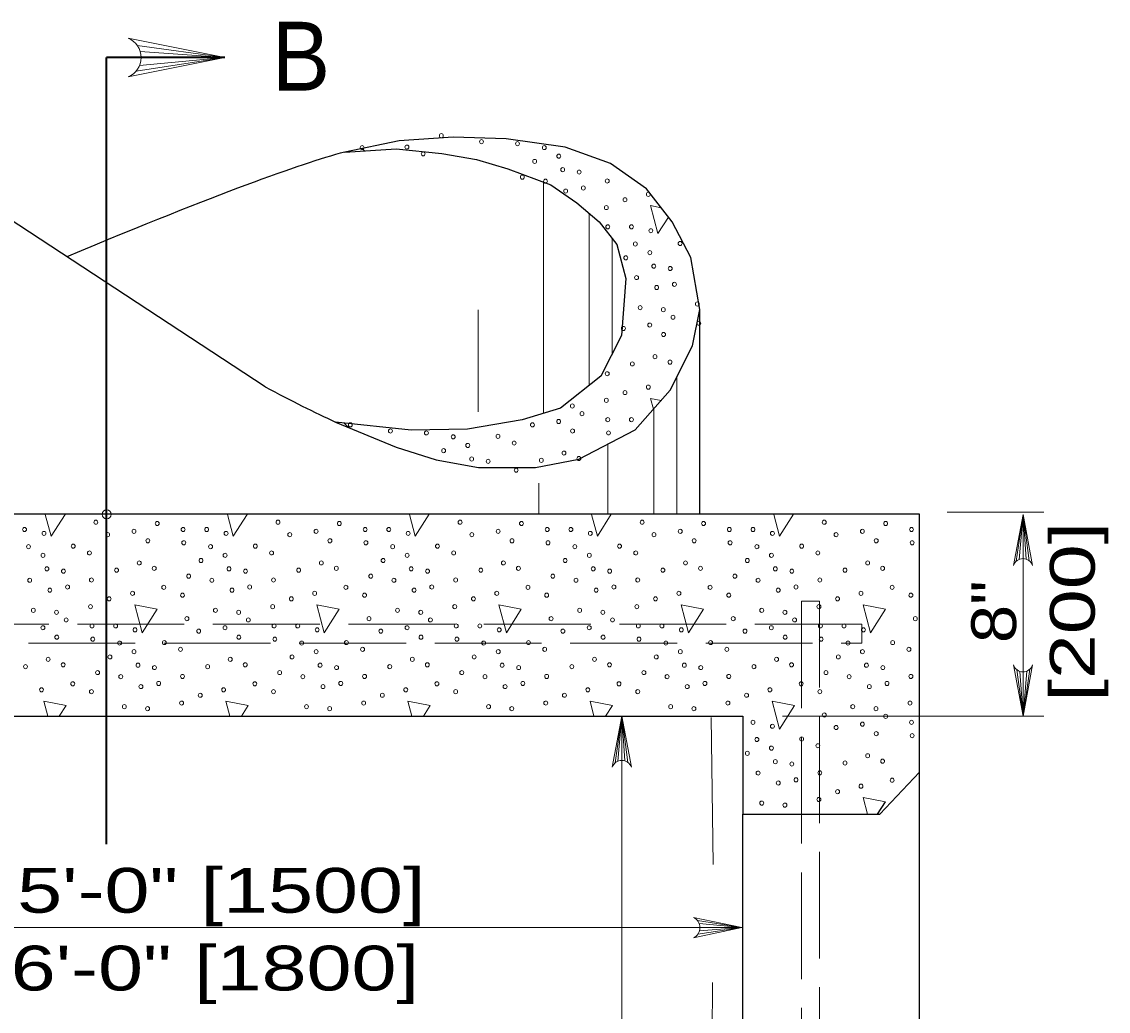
# Model space of a CAD drawing. Extents: x 1329.9 to 1363.9, y 715.5 to 737.5.
# Drawn here: x 1350.356 to 1354.141, y 722.725 to 726.171 of the extents above; entities that cross this region are included whole.
import ezdxf
from ezdxf.enums import TextEntityAlignment as Align

# ---------------------------------------------------------------- set-up
doc = ezdxf.new("R2010")
doc.units = 0
doc.header["$LTSCALE"] = 0.062
doc.header["$PDMODE"] = 32
doc.header["$PDSIZE"] = 0.031
doc.linetypes.add('LONG_DASHED', pattern=[7.5, 6, -1.5])
doc.layers.add('1', color=7, linetype='Continuous', lineweight=13)

msp = doc.modelspace()

# ---------------------------------------------------------------- linework, layer by layer
at = {"layer": '1'}
for p, q in [((1350.75792, 726.089), (1351.06258, 726.04642)), ((1350.75433, 725.99925), (1351.06258, 726.04642)), ((1350.766, 726.019), (1351.06258, 726.04642)), ((1350.76825, 726.06792), (1351.06258, 726.04642)), ((1350.77142, 726.04642), (1351.06258, 726.04642)), ((1351.54967, 725.72158), (1351.54183, 725.72975)), ((1352.17275, 724.80717), (1352.17275, 725.61258)), ((1352.58308, 725.5235), (1352.54617, 725.53067)), ((1352.33283, 724.90492), (1352.33283, 725.503)), ((1352.41283, 725.01583), (1352.41283, 725.41542)), ((1351.946, 724.8125), (1351.946, 725.1675)), ((1352.6375, 724.4555), (1352.6375, 724.93308)), ((1352.54617, 724.85908), (1352.55608, 724.82142)), ((1352.583, 724.85192), (1352.54617, 724.85908)), ((1352.5575, 724.4555), (1352.5575, 724.82267)), ((1351.45992, 724.77208), (1351.4565, 724.77592)), ((1351.494, 724.75825), (1351.47933, 724.7735)), ((1352.39742, 724.4555), (1352.39742, 724.69983)), ((1352.15733, 724.4555), (1352.15733, 724.56417)), ((1353.57942, 724.46342), (1353.916, 724.46342)), ((1353.82008, 724.29208), (1353.84367, 724.45525)), ((1353.83, 724.29825), (1353.84367, 724.45525)), ((1353.84367, 723.75258), (1353.84367, 724.45525)), ((1353.84367, 724.30108), (1353.84367, 724.45525)), ((1353.85442, 724.29942), (1353.84367, 724.45525)), ((1353.865, 724.294), (1353.84367, 724.45525)), ((1353.82233, 723.91383), (1353.84367, 723.75258)), ((1353.83292, 723.90833), (1353.84367, 723.75258)), ((1353.86717, 723.91575), (1353.84367, 723.75258)), ((1353.85733, 723.9095), (1353.84367, 723.75258)), ((1353.84367, 723.90667), (1353.84367, 723.75258)), ((1350.43217, 723.80475), (1350.44592, 723.75258)), ((1351.0665, 723.80475), (1351.08008, 723.75258)), ((1351.70092, 723.80475), (1351.71458, 723.75258)), ((1352.33533, 723.80475), (1352.34892, 723.75258)), ((1352.4225, 723.58942), (1352.44608, 723.75258)), ((1352.43242, 723.59558), (1352.44608, 723.75258)), ((1352.44608, 719.17433), (1352.44608, 723.75258)), ((1352.44608, 723.5985), (1352.44608, 723.75258)), ((1352.45683, 723.59683), (1352.44608, 723.75258)), ((1352.46733, 723.59133), (1352.44608, 723.75258)), ((1352.76375, 723.23608), (1352.75717, 723.74783)), ((1353.0055, 723.75258), (1353.916, 723.75258)), ((1353.28683, 723.469), (1353.30225, 723.41067)), ((1353.36475, 723.45375), (1353.28683, 723.469)), ((1348.49092, 723.01592), (1352.86367, 723.01592)), ((1352.70958, 723.04092), (1352.86367, 723.01592)), ((1352.71133, 722.99342), (1352.86367, 723.01592)), ((1352.71542, 723.03042), (1352.86367, 723.01592)), ((1352.7165, 723.00458), (1352.86367, 723.01592)), ((1352.71808, 723.01592), (1352.86367, 723.01592)), ((1352.75967, 722.31133), (1352.76208, 722.82492))]:
    msp.add_line(p, q, dxfattribs=at)
at = {"layer": '1', "lineweight": 35}
for p, q in [((1350.65133, 724.20842), (1350.65133, 726.04642)), ((1351.06258, 726.04642), (1350.65133, 726.04642)), ((1350.65133, 723.30692), (1350.65133, 724.20842))]:
    msp.add_line(p, q, dxfattribs=at)
at = {"layer": '1', "lineweight": 25}
for p, q in [((1351.20408, 724.89942), (1349.977, 725.70392)), ((1352.7175, 724.4555), (1352.7175, 725.16917)), ((1353.483, 719.36825), (1353.483, 723.55683)), ((1353.33733, 723.41067), (1353.36475, 723.45375)), ((1352.86742, 719.51625), (1352.86742, 723.41067))]:
    msp.add_line(p, q, dxfattribs=at)
at = {"layer": '1'}
for points in [[(1350.72608, 725.97908), (1351.06258, 726.04642), (1350.72608, 726.11367)], [(1351.48092, 725.71742), (1351.67067, 725.75608), (1351.859, 725.76933), (1352.04317, 725.76342), (1352.24817, 725.73458), (1352.40642, 725.677), (1352.53183, 725.58975), (1352.62117, 725.47442), (1352.6865, 725.35), (1352.7175, 725.16917), (1352.69208, 725.04292), (1352.615, 724.88808), (1352.49258, 724.74925), (1352.29633, 724.64725), (1352.14525, 724.619), (1351.94675, 724.61817), (1351.79875, 724.64583), (1351.6605, 724.68925), (1351.44875, 724.777)], [(1351.44875, 724.777), (1351.71258, 724.749), (1351.90892, 724.75233), (1352.09883, 724.78517), (1352.23275, 724.82492), (1352.37283, 724.93675), (1352.44458, 725.07883), (1352.46008, 725.27642), (1352.42883, 725.39508), (1352.36667, 725.47442), (1352.28883, 725.54033), (1352.19833, 725.60308), (1352.049, 725.65883), (1351.93983, 725.69192), (1351.8185, 725.71175), (1351.65967, 725.72833), (1351.48092, 725.71742)], [(1352.54617, 725.53067), (1352.57183, 725.43333), (1352.60833, 725.491)], [(1350.43758, 724.45542), (1350.45775, 724.37908), (1350.50633, 724.45542)], [(1351.072, 724.45542), (1351.09217, 724.37908), (1351.14067, 724.45542)], [(1351.70633, 724.45542), (1351.7265, 724.37908), (1351.77508, 724.4555)], [(1352.34075, 724.45542), (1352.36092, 724.37908), (1352.40942, 724.4555)], [(1352.97517, 724.45542), (1352.99533, 724.37908), (1353.04383, 724.4555)], [(1353.81, 724.27717), (1353.84367, 724.45525), (1353.87733, 724.27717)], [(1353.87733, 723.93067), (1353.84367, 723.75258), (1353.81, 723.93067)], [(1350.4865, 723.75267), (1350.50992, 723.78958), (1350.43217, 723.80475)], [(1351.12083, 723.75258), (1351.14442, 723.78958), (1351.0665, 723.80475)], [(1351.75525, 723.75258), (1351.77875, 723.78958), (1351.70092, 723.80475)], [(1352.38958, 723.75258), (1352.41317, 723.78958), (1352.33533, 723.80475)], [(1352.41242, 723.5745), (1352.44608, 723.75258), (1352.47975, 723.5745)], [(1352.69542, 723.05158), (1352.86367, 723.01592), (1352.69542, 722.98033)]]:
    msp.add_lwpolyline(points, dxfattribs=at)
at = {"layer": '1', "lineweight": 25}
for points in [[(1351.44875, 724.777), (1351.6605, 724.68925), (1351.79875, 724.64583), (1351.94675, 724.61817), (1352.14525, 724.619), (1352.29633, 724.64725), (1352.49258, 724.74925), (1352.615, 724.88808), (1352.69208, 725.04292), (1352.7175, 725.16917), (1352.6865, 725.35), (1352.62117, 725.47442), (1352.53183, 725.58975), (1352.40642, 725.677), (1352.24817, 725.73458), (1352.04317, 725.76342), (1351.859, 725.76933), (1351.67067, 725.75608), (1351.48092, 725.71742)], [(1351.44875, 724.777), (1351.6605, 724.68925), (1351.79875, 724.64583), (1351.94675, 724.61817), (1352.14525, 724.619), (1352.29633, 724.64725), (1352.49258, 724.74925), (1352.615, 724.88808), (1352.69208, 725.04292), (1352.7175, 725.16917), (1352.6865, 725.35), (1352.62117, 725.47442), (1352.53183, 725.58975), (1352.40642, 725.677), (1352.24817, 725.73458), (1352.04317, 725.76342), (1351.859, 725.76933), (1351.67067, 725.75608), (1351.48092, 725.71742)], [(1351.48092, 725.71742), (1351.65967, 725.72833), (1351.8185, 725.71175), (1351.93983, 725.69192), (1352.049, 725.65883), (1352.19833, 725.60308), (1352.28883, 725.54033), (1352.36667, 725.47442), (1352.42883, 725.39508), (1352.46008, 725.27642), (1352.44458, 725.07883), (1352.37283, 724.93675), (1352.23275, 724.82492), (1352.09883, 724.78517), (1351.90892, 724.75233), (1351.71258, 724.749), (1351.44875, 724.777)], [(1351.48092, 725.71742), (1351.65967, 725.72833), (1351.8185, 725.71175), (1351.93983, 725.69192), (1352.049, 725.65883), (1352.19833, 725.60308), (1352.28883, 725.54033), (1352.36667, 725.47442), (1352.42883, 725.39508), (1352.46008, 725.27642), (1352.44458, 725.07883), (1352.37283, 724.93675), (1352.23275, 724.82492), (1352.09883, 724.78517), (1351.90892, 724.75233), (1351.71258, 724.749), (1351.44875, 724.777)], [(1353.483, 723.55867), (1353.483, 724.4555), (1347.83075, 724.4555), (1347.83075, 723.58692)], [(1348.49467, 723.75258), (1352.86742, 723.75258), (1352.86742, 723.41067), (1353.34492, 723.41067), (1353.483, 723.55683)]]:
    msp.add_lwpolyline(points, dxfattribs=at)
at = {"layer": '1', "linetype": 'LONG_DASHED'}
for points in [[(1353.13433, 724.15242), (1353.07167, 724.15242), (1353.07167, 718.66), (1353.13433, 718.66)], [(1348.01858, 724.00633), (1353.28167, 724.00633), (1353.28167, 724.07267), (1348.01858, 724.07267)]]:
    msp.add_lwpolyline(points, close=True, dxfattribs=at)
at = {"layer": '1'}
for points in [[(1350.74925, 724.14058), (1350.77492, 724.04325), (1350.82717, 724.12542)], [(1351.38375, 724.14058), (1351.40942, 724.04325), (1351.46158, 724.12542)], [(1352.01808, 724.14058), (1352.04375, 724.04325), (1352.09592, 724.12542)], [(1352.6525, 724.14058), (1352.67817, 724.04325), (1352.73042, 724.12542)], [(1353.28683, 724.14058), (1353.3125, 724.04325), (1353.36475, 724.12542)], [(1352.96975, 723.80475), (1352.99533, 723.7075), (1353.04758, 723.78958)]]:
    msp.add_lwpolyline(points, close=True, dxfattribs=at)
msp.add_arc((1350.69893, 726.04646), 0.07261, 292.08605, 67.91218, dxfattribs=at)
for centre in [(1351.81734, 725.77454), (1351.69739, 725.73464), (1351.95723, 725.75339), (1352.08252, 725.74645), (1351.54154, 725.73285), (1351.7539, 725.71107), (1352.17594, 725.73285), (1352.22642, 725.7029), (1352.14247, 725.68477), (1352.09939, 725.63008), (1352.24017, 725.65577), (1352.29753, 725.64755), (1352.18017, 725.61587), (1352.31207, 725.5923), (1352.39517, 725.61671), (1352.25037, 725.58139), (1352.45708, 725.55117), (1352.5385, 725.5702), (1352.39206, 725.52396), (1352.39718, 725.45686), (1352.47944, 725.45686), (1352.54706, 725.44325), (1352.49314, 725.39702), (1352.64899, 725.39881), (1352.54362, 725.36708), (1352.45967, 725.34894), (1352.55737, 725.31995), (1352.49737, 725.28004), (1352.61473, 725.31172), (1352.56757, 725.24557), (1352.62927, 725.25648), (1352.50995, 725.17549), (1352.59078, 725.1685), (1352.70925, 725.18814), (1352.62446, 725.14191), (1352.45174, 725.1029), (1352.54336, 725.11471), (1352.71438, 725.12103), (1352.59163, 725.08174), (1352.48283, 724.97932), (1352.56165, 725.00467), (1352.61388, 724.98564), (1352.39517, 724.94506), (1352.45708, 724.87952), (1352.5385, 724.89855), (1352.27358, 724.83267), (1352.39206, 724.85232), (1352.30726, 724.80609), (1351.50014, 724.76708), (1352.13454, 724.76708), (1352.22616, 724.77888), (1352.39718, 724.78521), (1352.47944, 724.78521), (1351.64003, 724.74592), (1351.76532, 724.73898), (1351.85874, 724.72538), (1352.01459, 724.72717), (1352.27443, 724.74592), (1352.39972, 724.73898), (1351.82527, 724.6773), (1351.90923, 724.69543), (1352.0711, 724.7036), (1351.92297, 724.64831), (1351.98033, 724.64008), (1352.16563, 724.64349), (1352.24445, 724.66885), (1352.29668, 724.64982), (1352.07798, 724.60924), (1350.61375, 724.428), (1350.8276, 724.42346), (1351.24815, 724.428), (1351.462, 724.42346), (1351.88255, 724.428), (1352.0964, 724.42346), (1352.51695, 724.428), (1352.7308, 724.42346), (1353.15135, 724.428), (1353.36519, 724.42346), (1350.36539, 724.40259), (1350.433, 724.38898), (1350.65488, 724.38445), (1350.7465, 724.39626), (1350.91753, 724.40259), (1350.99979, 724.40259), (1351.0674, 724.38898), (1351.28928, 724.38445), (1351.3809, 724.39626), (1351.55192, 724.40259), (1351.63419, 724.40259), (1351.7018, 724.38898), (1351.92368, 724.38445), (1352.0153, 724.39626), (1352.18632, 724.40259), (1352.26858, 724.40259), (1352.3362, 724.38898), (1352.55808, 724.38445), (1352.6497, 724.39626), (1352.82072, 724.40259), (1352.90298, 724.40259), (1352.9706, 724.38898), (1353.19248, 724.38445), (1353.2841, 724.39626), (1353.45512, 724.40259), (1350.37908, 724.34275), (1350.53493, 724.34454), (1350.79477, 724.36329), (1350.92006, 724.35635), (1351.01348, 724.34275), (1351.16933, 724.34454), (1351.42917, 724.36329), (1351.55446, 724.35635), (1351.64788, 724.34275), (1351.80373, 724.34454), (1352.06357, 724.36329), (1352.18886, 724.35635), (1352.28228, 724.34275), (1352.43813, 724.34454), (1352.69797, 724.36329), (1352.82326, 724.35635), (1352.91667, 724.34275), (1353.07253, 724.34454), (1353.33236, 724.36329), (1353.45766, 724.35635), (1350.42957, 724.31281), (1350.59144, 724.32098), (1350.98001, 724.29467), (1351.06397, 724.31281), (1351.22584, 724.32098), (1351.61441, 724.29467), (1351.69837, 724.31281), (1351.86024, 724.32098), (1352.24881, 724.29467), (1352.33276, 724.31281), (1352.49464, 724.32098), (1352.88321, 724.29467), (1352.96716, 724.31281), (1353.12904, 724.32098), (1350.44331, 724.26568), (1350.50067, 724.25745), (1350.68597, 724.26087), (1350.76479, 724.28622), (1350.81703, 724.26719), (1351.07771, 724.26568), (1351.13507, 724.25745), (1351.32037, 724.26087), (1351.39919, 724.28622), (1351.45143, 724.26719), (1351.71211, 724.26568), (1351.76947, 724.25745), (1351.95477, 724.26087), (1352.03359, 724.28622), (1352.08582, 724.26719), (1352.34651, 724.26568), (1352.40387, 724.25745), (1352.58917, 724.26087), (1352.66799, 724.28622), (1352.72022, 724.26719), (1352.98091, 724.26568), (1353.03827, 724.25745), (1353.22357, 724.26087), (1353.30239, 724.28622), (1353.35462, 724.26719), (1350.38331, 724.22577), (1350.59832, 724.22661), (1350.93693, 724.23999), (1351.01771, 724.22577), (1351.23272, 724.22661), (1351.57133, 724.23999), (1351.65211, 724.22577), (1351.86712, 724.22661), (1352.20573, 724.23999), (1352.28651, 724.22577), (1352.50151, 724.22661), (1352.84012, 724.23999), (1352.9209, 724.22577), (1353.13591, 724.22661), (1350.45352, 724.1913), (1350.51521, 724.20221), (1350.85039, 724.20098), (1351.08791, 724.1913), (1351.14961, 724.20221), (1351.48478, 724.20098), (1351.72231, 724.1913), (1351.78401, 724.20221), (1352.11918, 724.20098), (1352.35671, 724.1913), (1352.41841, 724.20221), (1352.75358, 724.20098), (1352.99111, 724.1913), (1353.05281, 724.20221), (1353.38798, 724.20098), (1350.66022, 724.16107), (1350.74164, 724.1801), (1350.91552, 724.17378), (1351.29462, 724.16107), (1351.37604, 724.1801), (1351.54992, 724.17378), (1351.92902, 724.16107), (1352.01044, 724.1801), (1352.18431, 724.17378), (1352.56342, 724.16107), (1352.64484, 724.1801), (1352.81871, 724.17378), (1353.19782, 724.16107), (1353.27923, 724.1801), (1353.45311, 724.17378), (1350.39589, 724.12122), (1350.47672, 724.11423), (1350.5952, 724.13387), (1351.03029, 724.12122), (1351.11112, 724.11423), (1351.2296, 724.13387), (1351.66469, 724.12122), (1351.74552, 724.11423), (1351.864, 724.13387), (1352.29909, 724.12122), (1352.37992, 724.11423), (1352.49839, 724.13387), (1352.93349, 724.12122), (1353.01432, 724.11423), (1353.13279, 724.13387), (1350.5104, 724.08764), (1350.93095, 724.09217), (1351.1448, 724.08764), (1351.56535, 724.09217), (1351.7792, 724.08764), (1352.19975, 724.09217), (1352.4136, 724.08764), (1352.83415, 724.09217), (1353.048, 724.08764), (1353.46855, 724.09217), (1350.4293, 724.06044), (1350.60033, 724.06676), (1350.68259, 724.06676), (1350.7502, 724.05316), (1350.97208, 724.04863), (1351.0637, 724.06044), (1351.23473, 724.06676), (1351.31699, 724.06676), (1351.3846, 724.05316), (1351.60648, 724.04863), (1351.6981, 724.06044), (1351.86912, 724.06676), (1351.95138, 724.06676), (1352.019, 724.05316), (1352.24088, 724.04863), (1352.3325, 724.06044), (1352.50352, 724.06676), (1352.58578, 724.06676), (1352.6534, 724.05316), (1352.87528, 724.04863), (1352.9669, 724.06044), (1353.13792, 724.06676), (1353.22018, 724.06676), (1353.2878, 724.05316), (1350.47757, 724.02747), (1350.60286, 724.02053), (1350.69628, 724.00693), (1350.85213, 724.00872), (1351.11197, 724.02747), (1351.23726, 724.02053), (1351.33068, 724.00693), (1351.48653, 724.00872), (1351.74637, 724.02747), (1351.87166, 724.02053), (1351.96508, 724.00693), (1352.12093, 724.00872), (1352.38077, 724.02747), (1352.50606, 724.02053), (1352.59948, 724.00693), (1352.75533, 724.00872), (1353.01517, 724.02747), (1353.14046, 724.02053), (1353.23387, 724.00693), (1353.38972, 724.00872), (1350.66281, 723.95885), (1350.74677, 723.97699), (1350.90864, 723.98516), (1351.29721, 723.95885), (1351.38117, 723.97699), (1351.54304, 723.98516), (1351.93161, 723.95885), (1352.01556, 723.97699), (1352.17744, 723.98516), (1352.56601, 723.95885), (1352.64996, 723.97699), (1352.81184, 723.98516), (1353.20041, 723.95885), (1353.28436, 723.97699), (1353.44624, 723.98516), (1350.36877, 723.92505), (1350.4476, 723.9504), (1350.49983, 723.93137), (1350.76051, 723.92986), (1350.81787, 723.92163), (1351.00317, 723.92505), (1351.08199, 723.9504), (1351.13423, 723.93137), (1351.39491, 723.92986), (1351.45227, 723.92163), (1351.63757, 723.92505), (1351.71639, 723.9504), (1351.76862, 723.93137), (1352.02931, 723.92986), (1352.08667, 723.92163), (1352.27197, 723.92505), (1352.35079, 723.9504), (1352.40302, 723.93137), (1352.66371, 723.92986), (1352.72107, 723.92163), (1352.90637, 723.92505), (1352.98519, 723.9504), (1353.03742, 723.93137), (1353.29811, 723.92986), (1353.35547, 723.92163), (1350.61973, 723.90417), (1350.70051, 723.88995), (1350.91552, 723.89079), (1351.25413, 723.90417), (1351.33491, 723.88995), (1351.54992, 723.89079), (1351.88853, 723.90417), (1351.96931, 723.88995), (1352.18431, 723.89079), (1352.52292, 723.90417), (1352.6037, 723.88995), (1352.81871, 723.89079), (1353.15732, 723.90417), (1353.2381, 723.88995), (1353.45311, 723.89079), (1350.42444, 723.84428), (1350.53319, 723.86516), (1350.77072, 723.85547), (1350.83241, 723.86639), (1351.05884, 723.84428), (1351.16758, 723.86516), (1351.40511, 723.85547), (1351.46681, 723.86639), (1351.69324, 723.84428), (1351.80198, 723.86516), (1352.03951, 723.85547), (1352.10121, 723.86639), (1352.32764, 723.84428), (1352.43638, 723.86516), (1352.67391, 723.85547), (1352.73561, 723.86639), (1352.96203, 723.84428), (1353.07078, 723.86516), (1353.30831, 723.85547), (1353.37001, 723.86639), (1350.59832, 723.83796), (1350.97742, 723.82525), (1351.23272, 723.83796), (1351.61182, 723.82525), (1351.86712, 723.83796), (1352.24622, 723.82525), (1352.50151, 723.83796), (1352.88062, 723.82525), (1353.13591, 723.83796), (1350.71309, 723.7854), (1350.79392, 723.7784), (1350.9124, 723.79805), (1351.34749, 723.7854), (1351.42832, 723.7784), (1351.5468, 723.79805), (1351.98189, 723.7854), (1352.06272, 723.7784), (1352.1812, 723.79805), (1352.61629, 723.7854), (1352.69712, 723.7784), (1352.81559, 723.79805), (1353.25069, 723.7854), (1353.33152, 723.7784), (1353.44999, 723.79805), (1352.90298, 723.73094), (1353.15135, 723.75635), (1353.36519, 723.75182), (1353.45512, 723.73094), (1352.9706, 723.71734), (1353.19248, 723.71281), (1353.2841, 723.72462), (1353.33236, 723.69165), (1352.91667, 723.67111), (1353.07253, 723.6729), (1353.45766, 723.68471), (1352.88321, 723.62303), (1352.96716, 723.64116), (1353.12904, 723.64933), (1353.30239, 723.61458), (1352.98091, 723.59404), (1353.03827, 723.58581), (1353.22357, 723.58922), (1353.35462, 723.59555), (1352.9209, 723.55413), (1353.13591, 723.55497), (1352.99111, 723.51965), (1353.05281, 723.53057), (1353.27923, 723.50846), (1353.38798, 723.52933), (1353.13279, 723.46223), (1353.19782, 723.48943), (1352.93349, 723.44958), (1353.01432, 723.44258)]:
    msp.add_ellipse(centre, major_axis=(0, 0.00718), ratio=0.944544, dxfattribs=at)
for centre, major_axis, start_param, end_param in [((1353.84366, 724.26268), (0, 0.03844), 5.0978942, 7.4685073), ((1353.84365, 723.94513), (0, -0.03844), 5.0978942, 7.4685073), ((1352.44606, 723.56003), (0, 0.03844), 5.0978942, 7.4685073), ((1352.6818, 723.01594), (0, -0.03844), 0.3855052, 2.7561184)]:
    msp.add_ellipse(centre, major_axis=major_axis, ratio=0.944544, start_param=start_param, end_param=end_param, dxfattribs=at)
at = {"layer": '1', "lineweight": 25}
for points in [[(1351.48092, 725.71742), (1351.31592, 725.67217), (1351.05092, 725.57733), (1350.51292, 725.35258)], [(1351.20408, 724.89942), (1351.29425, 724.85117), (1351.37567, 724.81075), (1351.44875, 724.777)]]:
    msp.add_open_spline(points, degree=3, dxfattribs=at)
at = {"layer": '1'}
msp.add_point((1350.65133, 724.4555), dxfattribs=at)

# ---------------------------------------------------------------- texts
at = {"layer": '1', "width": 0.95}
msp.add_text('B', height=0.24, dxfattribs=at).set_placement((1351.32825, 725.93125), align=Align.CENTER)
at = {"layer": '1'}
for s, width, p in [('[200]', 1.35, (1354.09367, 724.11617)), ('8"', 1.15, (1353.81958, 724.11617))]:
    msp.add_text(s, height=0.156, rotation=90, dxfattribs=dict(at, width=width)).set_placement(p, align=Align.CENTER)
at = {"layer": '1', "width": 1.35}
for s, p in [('CB No. 2-5=5\'-0" [1500]', (1348.78225, 723.06783)), ('CB No. 2-6=6\'-0" [1800]', (1348.75983, 722.79692))]:
    msp.add_text(s, height=0.156, dxfattribs=at).set_placement(p)

doc.saveas('drawing.dxf')
